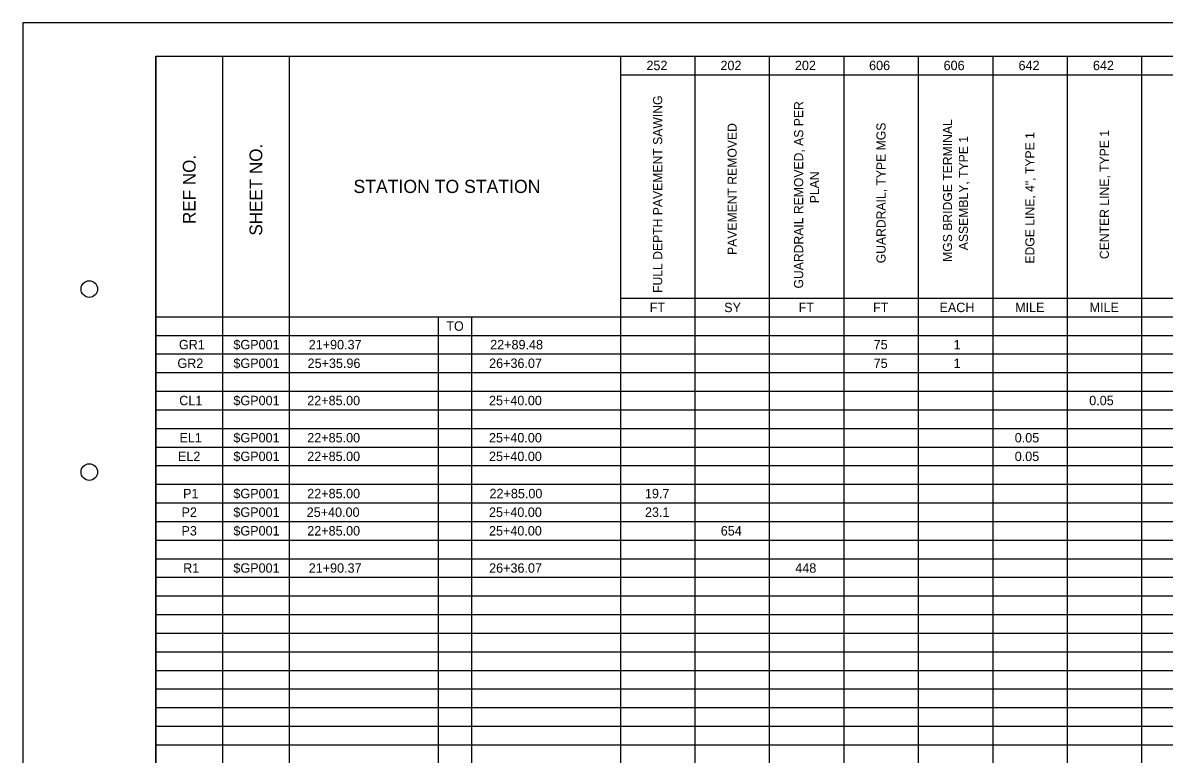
# Model space of a CAD drawing. Extents: x 0 to 34, y 0 to 22.
# Drawn here: x 0 to 17.17, y 11.01 to 22 of the extents above; entities that cross this region are included whole.
import ezdxf

# ---------------------------------------------------------------- set-up
doc = ezdxf.new("R2010")
doc.units = 0
for name, color, linetype in [('SH_Border', 7, 'Continuous'), ('SH_Cut_Line', 7, 'Continuous'), ('SH_Data', 7, 'Continuous'), ('SH_Text', 7, 'Continuous')]:
    doc.layers.add(name, color=color, linetype=linetype)

msp = doc.modelspace()

# ---------------------------------------------------------------- linework, layer by layer
at = {"layer": 'SH_Border'}
msp.add_lwpolyline([(2, 21.5), (33.5, 21.5), (33.5, 0.5), (2, 0.5)], close=True, dxfattribs=at)
for centre in [(1, 18), (1, 15.25)]:
    msp.add_circle(centre, 0.125, dxfattribs=at)
at = {"layer": 'SH_Cut_Line'}
msp.add_lwpolyline([(0, 0), (34, 0), (34, 22), (0, 22)], close=True, dxfattribs=at)
at = {"layer": 'SH_Data'}
for p, q in [((2, 21.5), (6.247, 21.5)), ((2, 21.5), (2, 20.381)), ((3.004, 21.5), (3.004, 20.381)), ((4.008, 21.5), (4.008, 20.381)), ((6.247, 21.5), (6.749, 21.5)), ((6.749, 21.5), (8.216, 21.5)), ((8.216, 21.5), (10.108, 21.5)), ((8.988, 21.5), (8.988, 20.381)), ((10.108, 21.5), (11.227, 21.5)), ((10.108, 21.5), (10.108, 20.381)), ((11.227, 21.5), (12.347, 21.5)), ((11.227, 21.5), (11.227, 20.381)), ((12.347, 21.5), (15.706, 21.5)), ((12.347, 21.5), (12.347, 20.381)), ((13.466, 21.5), (13.466, 20.381)), ((14.586, 21.5), (14.586, 20.381)), ((15.706, 21.5), (17.945, 21.5)), ((15.706, 21.5), (15.706, 20.381)), ((16.825, 21.5), (16.825, 20.381)), ((8.988, 21.22), (10.108, 21.22)), ((10.108, 21.22), (11.227, 21.22)), ((11.227, 21.22), (12.347, 21.22)), ((12.347, 21.22), (15.706, 21.22)), ((15.706, 21.22), (17.945, 21.22)), ((2, 20.381), (2, 18.983)), ((3.004, 20.381), (3.004, 18.983)), ((4.008, 20.381), (4.008, 18.983)), ((8.988, 20.381), (8.988, 18.983)), ((10.108, 20.381), (10.108, 18.983)), ((11.227, 20.381), (11.227, 18.983)), ((12.347, 20.381), (12.347, 18.983)), ((13.466, 20.381), (13.466, 18.983)), ((14.586, 20.381), (14.586, 18.983)), ((15.706, 20.381), (15.706, 18.983)), ((16.825, 20.381), (16.825, 18.983)), ((2, 18.983), (2, 18.143)), ((3.004, 18.983), (3.004, 18.143)), ((4.008, 18.983), (4.008, 18.143)), ((8.988, 18.983), (8.988, 18.143)), ((10.108, 18.983), (10.108, 18.143)), ((11.227, 18.983), (11.227, 18.143)), ((12.347, 18.983), (12.347, 18.143)), ((13.466, 18.983), (13.466, 18.143)), ((14.586, 18.983), (14.586, 18.143)), ((15.706, 18.983), (15.706, 18.143)), ((16.825, 18.983), (16.825, 18.143)), ((2, 18.143), (2, 17.864)), ((3.004, 18.143), (3.004, 17.864)), ((4.008, 18.143), (4.008, 17.864)), ((8.988, 18.143), (8.988, 17.864)), ((10.108, 18.143), (10.108, 17.864)), ((11.227, 18.143), (11.227, 17.864)), ((12.347, 18.143), (12.347, 17.864)), ((13.466, 18.143), (13.466, 17.864)), ((14.586, 18.143), (14.586, 17.864)), ((15.706, 18.143), (15.706, 17.864)), ((16.825, 18.143), (16.825, 17.864)), ((2, 17.864), (2, 17.584)), ((3.004, 17.864), (3.004, 17.584)), ((4.008, 17.864), (4.008, 17.584)), ((8.988, 17.864), (10.108, 17.864)), ((8.988, 17.864), (8.988, 17.584)), ((10.108, 17.864), (11.227, 17.864)), ((10.108, 17.864), (10.108, 17.584)), ((11.227, 17.864), (12.347, 17.864)), ((11.227, 17.864), (11.227, 17.584)), ((12.347, 17.864), (15.706, 17.864)), ((12.347, 17.864), (12.347, 17.584)), ((13.466, 17.864), (13.466, 17.584)), ((14.586, 17.864), (14.586, 17.584)), ((15.706, 17.864), (17.945, 17.864)), ((15.706, 17.864), (15.706, 17.584)), ((16.825, 17.864), (16.825, 17.584)), ((2, 17.584), (6.247, 17.584)), ((2, 17.584), (2, 17.304)), ((3.004, 17.584), (3.004, 17.304)), ((4.008, 17.584), (4.008, 17.304)), ((6.247, 17.584), (6.749, 17.584)), ((6.247, 17.584), (6.247, 17.304)), ((6.749, 17.584), (8.216, 17.584)), ((6.749, 17.584), (6.749, 17.304)), ((8.216, 17.584), (10.108, 17.584)), ((8.988, 17.584), (8.988, 17.304)), ((10.108, 17.584), (11.227, 17.584)), ((10.108, 17.584), (10.108, 17.304)), ((11.227, 17.584), (12.347, 17.584)), ((11.227, 17.584), (11.227, 17.304)), ((12.347, 17.584), (15.706, 17.584)), ((12.347, 17.584), (12.347, 17.304)), ((13.466, 17.584), (13.466, 17.304)), ((14.586, 17.584), (14.586, 17.304)), ((15.706, 17.584), (17.945, 17.584)), ((15.706, 17.584), (15.706, 17.304)), ((16.825, 17.584), (16.825, 17.304)), ((2, 17.304), (6.247, 17.304)), ((2, 17.304), (2, 17.025)), ((3.004, 17.304), (3.004, 17.025)), ((4.008, 17.304), (4.008, 17.025)), ((6.247, 17.304), (6.749, 17.304)), ((6.247, 17.304), (6.247, 17.025)), ((6.749, 17.304), (8.216, 17.304)), ((6.749, 17.304), (6.749, 17.025)), ((8.216, 17.304), (10.108, 17.304)), ((8.988, 17.304), (8.988, 17.025)), ((10.108, 17.304), (11.227, 17.304)), ((10.108, 17.304), (10.108, 17.025)), ((11.227, 17.304), (12.347, 17.304)), ((11.227, 17.304), (11.227, 17.025)), ((12.347, 17.304), (15.706, 17.304)), ((12.347, 17.304), (12.347, 17.025)), ((13.466, 17.304), (13.466, 17.025)), ((14.586, 17.304), (14.586, 17.025)), ((15.706, 17.304), (17.945, 17.304)), ((15.706, 17.304), (15.706, 17.025)), ((16.825, 17.304), (16.825, 17.025)), ((2, 17.025), (6.247, 17.025)), ((2, 17.025), (2, 16.745)), ((3.004, 17.025), (3.004, 16.745)), ((4.008, 17.025), (4.008, 16.745)), ((6.247, 17.025), (6.749, 17.025)), ((6.247, 17.025), (6.247, 16.745)), ((6.749, 17.025), (8.216, 17.025)), ((6.749, 17.025), (6.749, 16.745)), ((8.216, 17.025), (10.108, 17.025)), ((8.988, 17.025), (8.988, 16.745)), ((10.108, 17.025), (11.227, 17.025)), ((10.108, 17.025), (10.108, 16.745)), ((11.227, 17.025), (12.347, 17.025)), ((11.227, 17.025), (11.227, 16.745)), ((12.347, 17.025), (15.706, 17.025)), ((12.347, 17.025), (12.347, 16.745)), ((13.466, 17.025), (13.466, 16.745)), ((14.586, 17.025), (14.586, 16.745)), ((15.706, 17.025), (17.945, 17.025)), ((15.706, 17.025), (15.706, 16.745)), ((16.825, 17.025), (16.825, 16.745)), ((2, 16.745), (6.247, 16.745)), ((2, 16.745), (2, 16.465)), ((3.004, 16.745), (3.004, 16.465)), ((4.008, 16.745), (4.008, 16.465)), ((6.247, 16.745), (6.749, 16.745)), ((6.247, 16.745), (6.247, 16.465)), ((6.749, 16.745), (8.216, 16.745)), ((6.749, 16.745), (6.749, 16.465)), ((8.216, 16.745), (10.108, 16.745)), ((8.988, 16.745), (8.988, 16.465)), ((10.108, 16.745), (11.227, 16.745)), ((10.108, 16.745), (10.108, 16.465)), ((11.227, 16.745), (12.347, 16.745)), ((11.227, 16.745), (11.227, 16.465)), ((12.347, 16.745), (15.706, 16.745)), ((12.347, 16.745), (12.347, 16.465)), ((13.466, 16.745), (13.466, 16.465)), ((14.586, 16.745), (14.586, 16.465)), ((15.706, 16.745), (17.945, 16.745)), ((15.706, 16.745), (15.706, 16.465)), ((16.825, 16.745), (16.825, 16.465)), ((2, 16.465), (6.247, 16.465)), ((2, 16.465), (2, 16.185)), ((3.004, 16.465), (3.004, 16.185)), ((4.008, 16.465), (4.008, 16.185)), ((6.247, 16.465), (6.749, 16.465)), ((6.247, 16.465), (6.247, 16.185)), ((6.749, 16.465), (8.216, 16.465)), ((6.749, 16.465), (6.749, 16.185)), ((8.216, 16.465), (10.108, 16.465)), ((8.988, 16.465), (8.988, 16.185)), ((10.108, 16.465), (11.227, 16.465)), ((10.108, 16.465), (10.108, 16.185)), ((11.227, 16.465), (12.347, 16.465)), ((11.227, 16.465), (11.227, 16.185)), ((12.347, 16.465), (15.706, 16.465)), ((12.347, 16.465), (12.347, 16.185)), ((13.466, 16.465), (13.466, 16.185)), ((14.586, 16.465), (14.586, 16.185)), ((15.706, 16.465), (17.945, 16.465)), ((15.706, 16.465), (15.706, 16.185)), ((16.825, 16.465), (16.825, 16.185)), ((2, 16.185), (6.247, 16.185)), ((2, 16.185), (2, 15.906)), ((3.004, 16.185), (3.004, 15.906)), ((4.008, 16.185), (4.008, 15.906)), ((6.247, 16.185), (6.749, 16.185)), ((6.247, 16.185), (6.247, 15.906)), ((6.749, 16.185), (8.216, 16.185)), ((6.749, 16.185), (6.749, 15.906)), ((8.216, 16.185), (10.108, 16.185)), ((8.988, 16.185), (8.988, 15.906)), ((10.108, 16.185), (11.227, 16.185)), ((10.108, 16.185), (10.108, 15.906)), ((11.227, 16.185), (12.347, 16.185)), ((11.227, 16.185), (11.227, 15.906)), ((12.347, 16.185), (15.706, 16.185)), ((12.347, 16.185), (12.347, 15.906)), ((13.466, 16.185), (13.466, 15.906)), ((14.586, 16.185), (14.586, 15.906)), ((15.706, 16.185), (17.945, 16.185)), ((15.706, 16.185), (15.706, 15.906)), ((16.825, 16.185), (16.825, 15.906)), ((2, 15.906), (6.247, 15.906)), ((2, 15.906), (2, 15.626)), ((3.004, 15.906), (3.004, 15.626)), ((4.008, 15.906), (4.008, 15.626)), ((6.247, 15.906), (6.749, 15.906)), ((6.247, 15.906), (6.247, 15.626)), ((6.749, 15.906), (8.216, 15.906)), ((6.749, 15.906), (6.749, 15.626)), ((8.216, 15.906), (10.108, 15.906)), ((8.988, 15.906), (8.988, 15.626)), ((10.108, 15.906), (11.227, 15.906)), ((10.108, 15.906), (10.108, 15.626)), ((11.227, 15.906), (12.347, 15.906)), ((11.227, 15.906), (11.227, 15.626)), ((12.347, 15.906), (15.706, 15.906)), ((12.347, 15.906), (12.347, 15.626)), ((13.466, 15.906), (13.466, 15.626)), ((14.586, 15.906), (14.586, 15.626)), ((15.706, 15.906), (17.945, 15.906)), ((15.706, 15.906), (15.706, 15.626)), ((16.825, 15.906), (16.825, 15.626)), ((2, 15.626), (6.247, 15.626)), ((2, 15.626), (2, 15.066)), ((3.004, 15.626), (3.004, 15.066)), ((4.008, 15.626), (4.008, 15.066)), ((6.247, 15.626), (6.749, 15.626)), ((6.247, 15.626), (6.247, 15.066)), ((6.749, 15.626), (8.216, 15.626)), ((6.749, 15.626), (6.749, 15.066)), ((8.216, 15.626), (10.108, 15.626)), ((8.988, 15.626), (8.988, 15.066)), ((10.108, 15.626), (11.227, 15.626)), ((10.108, 15.626), (10.108, 15.066)), ((11.227, 15.626), (12.347, 15.626)), ((11.227, 15.626), (11.227, 15.066)), ((12.347, 15.626), (15.706, 15.626)), ((12.347, 15.626), (12.347, 15.066)), ((13.466, 15.626), (13.466, 15.066)), ((14.586, 15.626), (14.586, 15.066)), ((15.706, 15.626), (17.945, 15.626)), ((15.706, 15.626), (15.706, 15.066)), ((16.825, 15.626), (16.825, 15.066)), ((2, 15.346), (6.247, 15.346)), ((6.247, 15.346), (6.749, 15.346)), ((6.749, 15.346), (8.216, 15.346)), ((8.216, 15.346), (10.108, 15.346)), ((10.108, 15.346), (11.227, 15.346)), ((11.227, 15.346), (12.347, 15.346)), ((12.347, 15.346), (15.706, 15.346)), ((15.706, 15.346), (17.945, 15.346)), ((2, 15.066), (6.247, 15.066)), ((2, 15.066), (2, 13.668)), ((3.004, 15.066), (3.004, 13.668)), ((4.008, 15.066), (4.008, 13.668)), ((6.247, 15.066), (6.749, 15.066)), ((6.247, 15.066), (6.247, 13.668)), ((6.749, 15.066), (8.216, 15.066)), ((6.749, 15.066), (6.749, 13.668)), ((8.216, 15.066), (10.108, 15.066)), ((8.988, 15.066), (8.988, 13.668)), ((10.108, 15.066), (11.227, 15.066)), ((10.108, 15.066), (10.108, 13.668)), ((11.227, 15.066), (12.347, 15.066)), ((11.227, 15.066), (11.227, 13.668)), ((12.347, 15.066), (15.706, 15.066)), ((12.347, 15.066), (12.347, 13.668)), ((13.466, 15.066), (13.466, 13.668)), ((14.586, 15.066), (14.586, 13.668)), ((15.706, 15.066), (17.945, 15.066)), ((15.706, 15.066), (15.706, 13.668)), ((16.825, 15.066), (16.825, 13.668)), ((2, 14.787), (6.247, 14.787)), ((6.247, 14.787), (6.749, 14.787)), ((6.749, 14.787), (8.216, 14.787)), ((8.216, 14.787), (10.108, 14.787)), ((10.108, 14.787), (11.227, 14.787)), ((11.227, 14.787), (12.347, 14.787)), ((12.347, 14.787), (15.706, 14.787)), ((15.706, 14.787), (17.945, 14.787)), ((2, 14.507), (6.247, 14.507)), ((6.247, 14.507), (6.749, 14.507)), ((6.749, 14.507), (8.216, 14.507)), ((8.216, 14.507), (10.108, 14.507)), ((10.108, 14.507), (11.227, 14.507)), ((11.227, 14.507), (12.347, 14.507)), ((12.347, 14.507), (15.706, 14.507)), ((15.706, 14.507), (17.945, 14.507)), ((2, 14.227), (6.247, 14.227)), ((6.247, 14.227), (6.749, 14.227)), ((6.749, 14.227), (8.216, 14.227)), ((8.216, 14.227), (10.108, 14.227)), ((10.108, 14.227), (11.227, 14.227)), ((11.227, 14.227), (12.347, 14.227)), ((12.347, 14.227), (15.706, 14.227)), ((15.706, 14.227), (17.945, 14.227)), ((2, 13.948), (6.247, 13.948)), ((6.247, 13.948), (6.749, 13.948)), ((6.749, 13.948), (8.216, 13.948)), ((8.216, 13.948), (10.108, 13.948)), ((10.108, 13.948), (11.227, 13.948)), ((11.227, 13.948), (12.347, 13.948)), ((12.347, 13.948), (15.706, 13.948)), ((15.706, 13.948), (17.945, 13.948)), ((2, 13.668), (6.247, 13.668)), ((2, 13.668), (2, 11.99)), ((3.004, 13.668), (3.004, 11.99)), ((4.008, 13.668), (4.008, 11.99)), ((6.247, 13.668), (6.749, 13.668)), ((6.247, 13.668), (6.247, 11.99)), ((6.749, 13.668), (8.216, 13.668)), ((6.749, 13.668), (6.749, 11.99)), ((8.216, 13.668), (10.108, 13.668)), ((8.988, 13.668), (8.988, 11.99)), ((10.108, 13.668), (11.227, 13.668)), ((10.108, 13.668), (10.108, 11.99)), ((11.227, 13.668), (12.347, 13.668)), ((11.227, 13.668), (11.227, 11.99)), ((12.347, 13.668), (15.706, 13.668)), ((12.347, 13.668), (12.347, 11.99)), ((13.466, 13.668), (13.466, 11.99)), ((14.586, 13.668), (14.586, 11.99)), ((15.706, 13.668), (17.945, 13.668)), ((15.706, 13.668), (15.706, 11.99)), ((16.825, 13.668), (16.825, 11.99)), ((2, 13.388), (6.247, 13.388)), ((6.247, 13.388), (6.749, 13.388)), ((6.749, 13.388), (8.216, 13.388)), ((8.216, 13.388), (10.108, 13.388)), ((10.108, 13.388), (11.227, 13.388)), ((11.227, 13.388), (12.347, 13.388)), ((12.347, 13.388), (15.706, 13.388)), ((15.706, 13.388), (17.945, 13.388)), ((2, 13.108), (6.247, 13.108)), ((6.247, 13.108), (6.749, 13.108)), ((6.749, 13.108), (8.216, 13.108)), ((8.216, 13.108), (10.108, 13.108)), ((10.108, 13.108), (11.227, 13.108)), ((11.227, 13.108), (12.347, 13.108)), ((12.347, 13.108), (15.706, 13.108)), ((15.706, 13.108), (17.945, 13.108)), ((2, 12.829), (6.247, 12.829)), ((6.247, 12.829), (6.749, 12.829)), ((6.749, 12.829), (8.216, 12.829)), ((8.216, 12.829), (10.108, 12.829)), ((10.108, 12.829), (11.227, 12.829)), ((11.227, 12.829), (12.347, 12.829)), ((12.347, 12.829), (15.706, 12.829)), ((15.706, 12.829), (17.945, 12.829)), ((2, 12.549), (6.247, 12.549)), ((6.247, 12.549), (6.749, 12.549)), ((6.749, 12.549), (8.216, 12.549)), ((8.216, 12.549), (10.108, 12.549)), ((10.108, 12.549), (11.227, 12.549)), ((11.227, 12.549), (12.347, 12.549)), ((12.347, 12.549), (15.706, 12.549)), ((15.706, 12.549), (17.945, 12.549)), ((2, 12.269), (6.247, 12.269)), ((6.247, 12.269), (6.749, 12.269)), ((6.749, 12.269), (8.216, 12.269)), ((8.216, 12.269), (10.108, 12.269)), ((10.108, 12.269), (11.227, 12.269)), ((11.227, 12.269), (12.347, 12.269)), ((12.347, 12.269), (15.706, 12.269)), ((15.706, 12.269), (17.945, 12.269)), ((2, 11.99), (6.247, 11.99)), ((2, 11.99), (2, 10.591)), ((3.004, 11.99), (3.004, 10.591)), ((4.008, 11.99), (4.008, 10.591)), ((6.247, 11.99), (6.749, 11.99)), ((6.247, 11.99), (6.247, 10.591)), ((6.749, 11.99), (8.216, 11.99)), ((6.749, 11.99), (6.749, 10.591)), ((8.216, 11.99), (10.108, 11.99)), ((8.988, 11.99), (8.988, 10.591)), ((10.108, 11.99), (11.227, 11.99)), ((10.108, 11.99), (10.108, 10.591)), ((11.227, 11.99), (12.347, 11.99)), ((11.227, 11.99), (11.227, 10.591)), ((12.347, 11.99), (15.706, 11.99)), ((12.347, 11.99), (12.347, 10.591)), ((13.466, 11.99), (13.466, 10.591)), ((14.586, 11.99), (14.586, 10.591)), ((15.706, 11.99), (17.945, 11.99)), ((15.706, 11.99), (15.706, 10.591)), ((16.825, 11.99), (16.825, 10.591)), ((2, 11.71), (6.247, 11.71)), ((6.247, 11.71), (6.749, 11.71)), ((6.749, 11.71), (8.216, 11.71)), ((8.216, 11.71), (10.108, 11.71)), ((10.108, 11.71), (11.227, 11.71)), ((11.227, 11.71), (12.347, 11.71)), ((12.347, 11.71), (15.706, 11.71)), ((15.706, 11.71), (17.945, 11.71)), ((2, 11.43), (6.247, 11.43)), ((6.247, 11.43), (6.749, 11.43)), ((6.749, 11.43), (8.216, 11.43)), ((8.216, 11.43), (10.108, 11.43)), ((10.108, 11.43), (11.227, 11.43)), ((11.227, 11.43), (12.347, 11.43)), ((12.347, 11.43), (15.706, 11.43)), ((15.706, 11.43), (17.945, 11.43)), ((2, 11.15), (6.247, 11.15)), ((6.247, 11.15), (6.749, 11.15)), ((6.749, 11.15), (8.216, 11.15)), ((8.216, 11.15), (10.108, 11.15)), ((10.108, 11.15), (11.227, 11.15)), ((11.227, 11.15), (12.347, 11.15)), ((12.347, 11.15), (15.706, 11.15)), ((15.706, 11.15), (17.945, 11.15))]:
    msp.add_line(p, q, dxfattribs=at)

# ---------------------------------------------------------------- texts
at = {"layer": 'SH_Text'}
for s, height, p in [('252', 0.1415, (9.379, 21.289)), ('202', 0.1415, (10.492, 21.289)), ('202', 0.1415, (11.612, 21.289)), ('606', 0.1415, (12.728, 21.289)), ('606', 0.1415, (13.848, 21.289)), ('642', 0.1415, (14.975, 21.289)), ('642', 0.1415, (16.094, 21.289)), ('STATION TO STATION', 0.19813, (4.973, 19.443)), ('FT', 0.1415, (9.428, 17.653)), ('SY', 0.1415, (10.548, 17.653)), ('FT', 0.1415, (11.668, 17.653)), ('FT', 0.1415, (12.787, 17.653)), ('EACH', 0.1415, (13.786, 17.653)), ('MILE', 0.1415, (14.924, 17.653)), ('MILE', 0.1415, (16.043, 17.653)), ('TO', 0.1415, (6.369, 17.373)), ('GR1', 0.1415, (2.348, 17.094)), ('$GP001', 0.1415, (3.167, 17.094)), ('21+90.37', 0.1415, (4.3, 17.094)), ('22+89.48', 0.1415, (7.029, 17.094)), ('75', 0.1415, (12.796, 17.094)), ('1', 0.142, (13.998, 17.094)), ('GR2', 0.1415, (2.325, 16.814)), ('$GP001', 0.1415, (3.167, 16.814)), ('25+35.96', 0.1415, (4.283, 16.814)), ('26+36.07', 0.1415, (7.013, 16.814)), ('75', 0.1415, (12.796, 16.814)), ('1', 0.142, (13.998, 16.814)), ('CL1', 0.1415, (2.352, 16.254)), ('$GP001', 0.1415, (3.167, 16.254)), ('22+85.00', 0.1415, (4.278, 16.254)), ('25+40.00', 0.1415, (7.011, 16.254)), ('0.05', 0.1415, (16.038, 16.254)), ('EL1', 0.1415, (2.356, 15.695)), ('$GP001', 0.1415, (3.167, 15.695)), ('22+85.00', 0.1415, (4.278, 15.695)), ('25+40.00', 0.1415, (7.011, 15.695)), ('0.05', 0.1415, (14.918, 15.695)), ('EL2', 0.1415, (2.333, 15.415)), ('$GP001', 0.1415, (3.167, 15.415)), ('22+85.00', 0.1415, (4.278, 15.415)), ('25+40.00', 0.1415, (7.011, 15.415)), ('0.05', 0.1415, (14.918, 15.415)), ('P1', 0.1415, (2.41, 14.856)), ('$GP001', 0.1415, (3.167, 14.856)), ('22+85.00', 0.1415, (4.278, 14.856)), ('22+85.00', 0.1415, (7.019, 14.856)), ('19.7', 0.1415, (9.356, 14.856)), ('P2', 0.1415, (2.387, 14.576)), ('$GP001', 0.1415, (3.167, 14.576)), ('25+40.00', 0.1415, (4.27, 14.576)), ('25+40.00', 0.1415, (7.011, 14.576)), ('23.1', 0.1415, (9.357, 14.576)), ('P3', 0.1415, (2.386, 14.296)), ('$GP001', 0.1415, (3.167, 14.296)), ('22+85.00', 0.1415, (4.278, 14.296)), ('25+40.00', 0.1415, (7.011, 14.296)), ('654', 0.1415, (10.497, 14.296)), ('R1', 0.1415, (2.411, 13.737)), ('$GP001', 0.1415, (3.167, 13.737)), ('21+90.37', 0.1415, (4.3, 13.737)), ('26+36.07', 0.1415, (7.013, 13.737)), ('448', 0.1415, (11.618, 13.737))]:
    msp.add_text(s, height=height, dxfattribs=at).set_placement(p)
for s, height, p in [('FULL DEPTH PAVEMENT SAWING', 0.13674, (9.616, 17.941)), ('GUARDRAIL REMOVED, AS PER', 0.13674, (11.736, 18.008)), ('PAVEMENT REMOVED', 0.13674, (10.736, 18.512)), ('GUARDRAIL, TYPE MGS', 0.13674, (12.975, 18.387)), ('MGS BRIDGE TERMINAL', 0.13674, (13.975, 18.408)), ('ASSEMBLY, TYPE 1', 0.13674, (14.214, 18.583)), ('EDGE LINE, 4", TYPE 1', 0.13674, (15.214, 18.382)), ('CENTER LINE, TYPE 1', 0.13674, (16.334, 18.45)), ('SHEET NO.', 0.1914, (3.601, 18.803)), ('REF NO.', 0.1914, (2.598, 18.977)), ('PLAN', 0.1367, (11.975, 19.289))]:
    msp.add_text(s, height=height, rotation=90, dxfattribs=at).set_placement(p)

doc.saveas('drawing.dxf')
